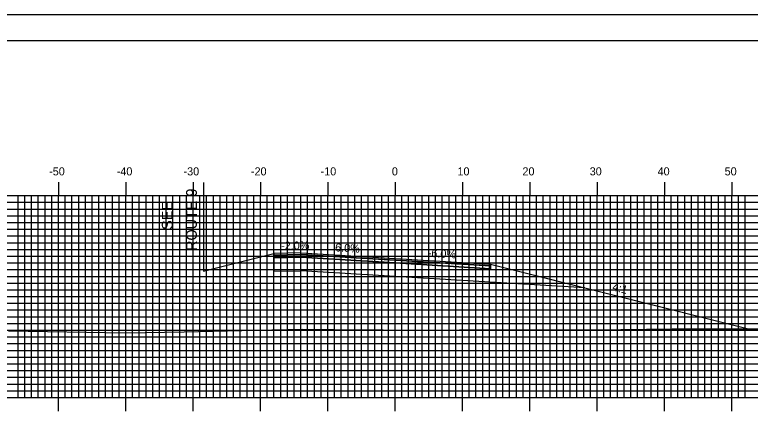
# Model space of a CAD drawing. Extents: x 2059 to 2403, y -1658 to -1438.
# Drawn here: x 2168.7 to 2277.9, y -1497.1 to -1437.7 of the extents above; entities that cross this region are included whole.
import ezdxf

# ---------------------------------------------------------------- set-up
doc = ezdxf.new("R2010")
doc.units = 0
for name, color, linetype in [('ANNOTATION', 7, 'Continuous'), ('BORDER', 7, 'Continuous'), ('D_Roadway_Centerline', 7, 'Continuous'), ('D_Roadway_Edge_Shoulder', 7, 'Continuous'), ('D_Roadway_Edge_TW', 7, 'Continuous'), ('D_Roadway_Pavement', 7, 'Continuous'), ('D_Roadway_SlopeLines', 7, 'Continuous'), ('D_Roadway_SubGrade', 7, 'Continuous'), ('H_V ANNOTATION', 7, 'Continuous'), ('MAJOR', 7, 'Continuous'), ('MINOR', 7, 'Continuous'), ('PLOT BOUNDARY', 7, 'Continuous'), ('S_Roadway_Centerline', 7, 'Continuous')]:
    doc.layers.add(name, color=color, linetype=linetype)

msp = doc.modelspace()

# ---------------------------------------------------------------- linework, layer by layer
at = {"layer": 'BORDER'}
msp.add_lwpolyline([(2075.59, -1651.6), (2395.59, -1651.6), (2395.59, -1441.6), (2075.59, -1441.6)], close=True, dxfattribs=at)
at = {"layer": 'D_Roadway_Centerline'}
msp.add_lwpolyline([(2196.7, -1475.81), (2198.84, -1475.27), (2207.19, -1473.19)], dxfattribs=at)
at = {"layer": 'D_Roadway_Edge_Shoulder'}
for points in [[(2211.19, -1473.11), (2207.19, -1473.19), (2207.19, -1473.44), (2211.19, -1473.36)], [(2211.19, -1473.11), (2207.19, -1473.19), (2207.19, -1473.44), (2211.19, -1473.36)], [(2225.19, -1473.95), (2239.33, -1474.8), (2239.33, -1475.05), (2225.19, -1474.2)]]:
    msp.add_lwpolyline(points, close=True, dxfattribs=at)
at = {"layer": 'D_Roadway_Edge_TW'}
msp.add_lwpolyline([(2211.19, -1473.11), (2225.19, -1473.95), (2225.19, -1474.2), (2211.19, -1473.36)], close=True, dxfattribs=at)
msp.add_lwpolyline([(2211.19, -1473.11), (2225.19, -1473.95), (2225.19, -1474.2), (2211.19, -1473.36)], close=True, dxfattribs=at)
msp.add_lwpolyline([(2211.19, -1473.11), (2225.19, -1473.95), (2225.19, -1474.2), (2211.19, -1473.36)], close=True, dxfattribs=at)
msp.add_lwpolyline([(2211.19, -1473.11), (2225.19, -1473.95), (2225.19, -1474.2), (2211.19, -1473.36)], close=True, dxfattribs=at)
at = {"layer": 'D_Roadway_Pavement'}
for points in [[(2211.19, -1473.36), (2207.19, -1473.44), (2207.19, -1473.85), (2211.19, -1473.77)], [(2211.19, -1473.36), (2207.19, -1473.44), (2207.19, -1473.85), (2211.19, -1473.77)], [(2211.19, -1473.36), (2225.19, -1474.2), (2225.19, -1474.61), (2211.19, -1473.77)], [(2211.19, -1473.36), (2225.19, -1474.2), (2225.19, -1474.61), (2211.19, -1473.77)], [(2211.19, -1473.36), (2225.19, -1474.2), (2225.19, -1474.61), (2211.19, -1473.77)], [(2211.19, -1473.36), (2225.19, -1474.2), (2225.19, -1474.61), (2211.19, -1473.77)], [(2225.19, -1474.2), (2239.33, -1475.05), (2239.33, -1475.46), (2225.19, -1474.61)]]:
    msp.add_lwpolyline(points, close=True, dxfattribs=at)
msp.add_lwpolyline([(2225.19, -1474.2), (2225.19, -1474.61)], dxfattribs=at)
msp.add_lwpolyline([(2225.19, -1474.2), (2225.19, -1474.61)], dxfattribs=at)
msp.add_lwpolyline([(2225.19, -1474.2), (2225.19, -1474.61)], dxfattribs=at)
msp.add_lwpolyline([(2225.19, -1474.2), (2225.19, -1474.61)], dxfattribs=at)
msp.add_lwpolyline([(2225.19, -1474.2), (2225.19, -1474.61)], dxfattribs=at)
msp.add_lwpolyline([(2225.19, -1474.2), (2225.19, -1474.61)], dxfattribs=at)
msp.add_lwpolyline([(2225.19, -1474.2), (2225.19, -1474.61)], dxfattribs=at)
msp.add_lwpolyline([(2225.19, -1474.2), (2225.19, -1474.61)], dxfattribs=at)
msp.add_lwpolyline([(2225.19, -1474.2), (2225.19, -1474.61)], dxfattribs=at)
msp.add_lwpolyline([(2225.19, -1474.2), (2225.19, -1474.61)], dxfattribs=at)
msp.add_lwpolyline([(2225.19, -1474.2), (2225.19, -1474.61)], dxfattribs=at)
msp.add_lwpolyline([(2225.19, -1474.2), (2225.19, -1474.61)], dxfattribs=at)
msp.add_lwpolyline([(2225.19, -1474.2), (2225.19, -1474.61)], dxfattribs=at)
msp.add_lwpolyline([(2225.19, -1474.2), (2225.19, -1474.61)], dxfattribs=at)
at = {"layer": 'D_Roadway_SlopeLines'}
msp.add_lwpolyline([(2239.33, -1474.8), (2277.67, -1484.38)], dxfattribs=at)
at = {"layer": 'D_Roadway_SubGrade'}
msp.add_line((2196.7, -1462.67), (2196.7, -1475.81), dxfattribs=at)
for points in [[(2211.19, -1473.77), (2207.19, -1473.85), (2207.19, -1473.44), (2207.19, -1475.85), (2211.19, -1475.77)], [(2211.19, -1473.77), (2225.19, -1474.61), (2225.19, -1476.61), (2211.19, -1475.77)], [(2211.19, -1473.77), (2225.19, -1474.61), (2225.19, -1476.61), (2211.19, -1475.77)], [(2211.19, -1473.77), (2225.19, -1474.61), (2225.19, -1476.61), (2211.19, -1475.77)], [(2211.19, -1473.77), (2225.19, -1474.61), (2225.19, -1476.61), (2211.19, -1475.77)], [(2225.19, -1474.61), (2225.19, -1474.2), (2239.33, -1475.05), (2239.33, -1474.8), (2253.37, -1478.3), (2225.19, -1476.61)], [(2225.19, -1474.61), (2225.19, -1474.2), (2239.33, -1475.05), (2239.33, -1474.8), (2253.37, -1478.3), (2225.19, -1476.61)], [(2225.19, -1474.61), (2239.33, -1475.46), (2239.33, -1475.05), (2239.33, -1474.8), (2253.37, -1478.3), (2225.19, -1476.61)]]:
    msp.add_lwpolyline(points, close=True, dxfattribs=at)
at = {"layer": 'MAJOR'}
for p, q in [((2175.19, -1462.6), (2175.19, -1464.6)), ((2185.19, -1462.6), (2185.19, -1464.6)), ((2195.19, -1462.6), (2195.19, -1464.6)), ((2205.19, -1462.6), (2205.19, -1464.6)), ((2215.19, -1462.6), (2215.19, -1464.6)), ((2225.19, -1462.6), (2225.19, -1464.6)), ((2235.19, -1462.6), (2235.19, -1464.6)), ((2245.19, -1462.6), (2245.19, -1464.6)), ((2255.19, -1462.6), (2255.19, -1464.6)), ((2265.19, -1462.6), (2265.19, -1464.6)), ((2275.19, -1462.6), (2275.19, -1464.6)), ((2085.19, -1464.6), (2365.19, -1464.6)), ((2085.19, -1464.6), (2365.19, -1464.6)), ((2175.19, -1494.6), (2175.19, -1464.6)), ((2185.19, -1494.6), (2185.19, -1464.6)), ((2195.19, -1494.6), (2195.19, -1464.6)), ((2205.19, -1494.6), (2205.19, -1464.6)), ((2215.19, -1494.6), (2215.19, -1464.6)), ((2225.19, -1494.6), (2225.19, -1464.6)), ((2235.19, -1494.6), (2235.19, -1464.6)), ((2245.19, -1494.6), (2245.19, -1464.6)), ((2255.19, -1494.6), (2255.19, -1464.6)), ((2265.19, -1494.6), (2265.19, -1464.6)), ((2275.19, -1494.6), (2275.19, -1464.6)), ((2085.19, -1469.6), (2365.19, -1469.6)), ((2085.19, -1474.6), (2365.19, -1474.6)), ((2085.19, -1479.6), (2365.19, -1479.6)), ((2085.19, -1484.6), (2365.19, -1484.6)), ((2085.19, -1489.6), (2365.19, -1489.6)), ((2085.19, -1494.6), (2365.19, -1494.6)), ((2085.19, -1494.6), (2365.19, -1494.6)), ((2175.19, -1496.61), (2175.19, -1494.6)), ((2185.19, -1496.61), (2185.19, -1494.6)), ((2195.19, -1496.61), (2195.19, -1494.6)), ((2205.19, -1496.61), (2205.19, -1494.6)), ((2215.19, -1496.61), (2215.19, -1494.6)), ((2225.19, -1496.61), (2225.19, -1494.6)), ((2235.19, -1496.61), (2235.19, -1494.6)), ((2245.19, -1496.61), (2245.19, -1494.6)), ((2255.19, -1496.61), (2255.19, -1494.6)), ((2265.19, -1496.61), (2265.19, -1494.6)), ((2275.19, -1496.61), (2275.19, -1494.6))]:
    msp.add_line(p, q, dxfattribs=at)
at = {"layer": 'MINOR'}
for p, q in [((2169.19, -1494.6), (2169.19, -1464.6)), ((2170.19, -1494.6), (2170.19, -1464.6)), ((2171.19, -1494.6), (2171.19, -1464.6)), ((2172.19, -1494.6), (2172.19, -1464.6)), ((2173.19, -1494.6), (2173.19, -1464.6)), ((2174.19, -1494.6), (2174.19, -1464.6)), ((2176.19, -1494.6), (2176.19, -1464.6)), ((2177.19, -1494.6), (2177.19, -1464.6)), ((2178.19, -1494.6), (2178.19, -1464.6)), ((2179.19, -1494.6), (2179.19, -1464.6)), ((2180.19, -1494.6), (2180.19, -1464.6)), ((2181.19, -1494.6), (2181.19, -1464.6)), ((2182.19, -1494.6), (2182.19, -1464.6)), ((2183.19, -1494.6), (2183.19, -1464.6)), ((2184.19, -1494.6), (2184.19, -1464.6)), ((2186.19, -1494.6), (2186.19, -1464.6)), ((2187.19, -1494.6), (2187.19, -1464.6)), ((2188.19, -1494.6), (2188.19, -1464.6)), ((2189.19, -1494.6), (2189.19, -1464.6)), ((2190.19, -1494.6), (2190.19, -1464.6)), ((2191.19, -1494.6), (2191.19, -1464.6)), ((2192.19, -1494.6), (2192.19, -1464.6)), ((2193.19, -1494.6), (2193.19, -1464.6)), ((2194.19, -1494.6), (2194.19, -1464.6)), ((2196.19, -1494.6), (2196.19, -1464.6)), ((2197.19, -1494.6), (2197.19, -1464.6)), ((2198.19, -1494.6), (2198.19, -1464.6)), ((2199.19, -1494.6), (2199.19, -1464.6)), ((2200.19, -1494.6), (2200.19, -1464.6)), ((2201.19, -1494.6), (2201.19, -1464.6)), ((2202.19, -1494.6), (2202.19, -1464.6)), ((2203.19, -1494.6), (2203.19, -1464.6)), ((2204.19, -1494.6), (2204.19, -1464.6)), ((2206.19, -1494.6), (2206.19, -1464.6)), ((2207.19, -1494.6), (2207.19, -1464.6)), ((2208.19, -1494.6), (2208.19, -1464.6)), ((2209.19, -1494.6), (2209.19, -1464.6)), ((2210.19, -1494.6), (2210.19, -1464.6)), ((2211.19, -1494.6), (2211.19, -1464.6)), ((2212.19, -1494.6), (2212.19, -1464.6)), ((2213.19, -1494.6), (2213.19, -1464.6)), ((2214.19, -1494.6), (2214.19, -1464.6)), ((2216.19, -1494.6), (2216.19, -1464.6)), ((2217.19, -1494.6), (2217.19, -1464.6)), ((2218.19, -1494.6), (2218.19, -1464.6)), ((2219.19, -1494.6), (2219.19, -1464.6)), ((2220.19, -1494.6), (2220.19, -1464.6)), ((2221.19, -1494.6), (2221.19, -1464.6)), ((2222.19, -1494.6), (2222.19, -1464.6)), ((2223.19, -1494.6), (2223.19, -1464.6)), ((2224.19, -1494.6), (2224.19, -1464.6)), ((2226.19, -1494.6), (2226.19, -1464.6)), ((2227.19, -1494.6), (2227.19, -1464.6)), ((2228.19, -1494.6), (2228.19, -1464.6)), ((2229.19, -1494.6), (2229.19, -1464.6)), ((2230.19, -1494.6), (2230.19, -1464.6)), ((2231.19, -1494.6), (2231.19, -1464.6)), ((2232.19, -1494.6), (2232.19, -1464.6)), ((2233.19, -1494.6), (2233.19, -1464.6)), ((2234.19, -1494.6), (2234.19, -1464.6)), ((2236.19, -1494.6), (2236.19, -1464.6)), ((2237.19, -1494.6), (2237.19, -1464.6)), ((2238.19, -1494.6), (2238.19, -1464.6)), ((2239.19, -1494.6), (2239.19, -1464.6)), ((2240.19, -1494.6), (2240.19, -1464.6)), ((2241.19, -1494.6), (2241.19, -1464.6)), ((2242.19, -1494.6), (2242.19, -1464.6)), ((2243.19, -1494.6), (2243.19, -1464.6)), ((2244.19, -1494.6), (2244.19, -1464.6)), ((2246.19, -1494.6), (2246.19, -1464.6)), ((2247.19, -1494.6), (2247.19, -1464.6)), ((2248.19, -1494.6), (2248.19, -1464.6)), ((2249.19, -1494.6), (2249.19, -1464.6)), ((2250.19, -1494.6), (2250.19, -1464.6)), ((2251.19, -1494.6), (2251.19, -1464.6)), ((2252.19, -1494.6), (2252.19, -1464.6)), ((2253.19, -1494.6), (2253.19, -1464.6)), ((2254.19, -1494.6), (2254.19, -1464.6)), ((2256.19, -1494.6), (2256.19, -1464.6)), ((2257.19, -1494.6), (2257.19, -1464.6)), ((2258.19, -1494.6), (2258.19, -1464.6)), ((2259.19, -1494.6), (2259.19, -1464.6)), ((2260.19, -1494.6), (2260.19, -1464.6)), ((2261.19, -1494.6), (2261.19, -1464.6)), ((2262.19, -1494.6), (2262.19, -1464.6)), ((2263.19, -1494.6), (2263.19, -1464.6)), ((2264.19, -1494.6), (2264.19, -1464.6)), ((2266.19, -1494.6), (2266.19, -1464.6)), ((2267.19, -1494.6), (2267.19, -1464.6)), ((2268.19, -1494.6), (2268.19, -1464.6)), ((2269.19, -1494.6), (2269.19, -1464.6)), ((2270.19, -1494.6), (2270.19, -1464.6)), ((2271.19, -1494.6), (2271.19, -1464.6)), ((2272.19, -1494.6), (2272.19, -1464.6)), ((2273.19, -1494.6), (2273.19, -1464.6)), ((2274.19, -1494.6), (2274.19, -1464.6)), ((2276.19, -1494.6), (2276.19, -1464.6)), ((2277.19, -1494.6), (2277.19, -1464.6)), ((2085.19, -1465.6), (2365.19, -1465.6)), ((2085.19, -1466.6), (2365.19, -1466.6)), ((2085.19, -1467.6), (2365.19, -1467.6)), ((2085.19, -1468.6), (2365.19, -1468.6)), ((2085.19, -1470.6), (2365.19, -1470.6)), ((2085.19, -1471.6), (2365.19, -1471.6)), ((2085.19, -1472.6), (2365.19, -1472.6)), ((2085.19, -1473.6), (2365.19, -1473.6)), ((2085.19, -1475.6), (2365.19, -1475.6)), ((2085.19, -1476.6), (2365.19, -1476.6)), ((2085.19, -1477.6), (2365.19, -1477.6)), ((2085.19, -1478.6), (2365.19, -1478.6)), ((2085.19, -1480.6), (2365.19, -1480.6)), ((2085.19, -1481.6), (2365.19, -1481.6)), ((2085.19, -1482.6), (2365.19, -1482.6)), ((2085.19, -1483.6), (2365.19, -1483.6)), ((2085.19, -1485.6), (2365.19, -1485.6)), ((2085.19, -1486.6), (2365.19, -1486.6)), ((2085.19, -1487.6), (2365.19, -1487.6)), ((2085.19, -1488.6), (2365.19, -1488.6)), ((2085.19, -1490.6), (2365.19, -1490.6)), ((2085.19, -1491.6), (2365.19, -1491.6)), ((2085.19, -1492.6), (2365.19, -1492.6)), ((2085.19, -1493.6), (2365.19, -1493.6))]:
    msp.add_line(p, q, dxfattribs=at)
at = {"layer": 'PLOT BOUNDARY'}
msp.add_lwpolyline([(2059.4, -1657.72), (2399.4, -1657.72), (2399.4, -1437.72), (2059.4, -1437.72)], close=True, dxfattribs=at)
at = {"layer": 'S_Roadway_Centerline'}
msp.add_lwpolyline([(2167.74, -1484.69), (2185.15, -1484.97), (2193.87, -1484.85), (2204.55, -1484.58), (2211.5, -1484.43), (2220.92, -1484.57), (2223.43, -1484.55), (2225.24, -1484.58), (2234.74, -1484.55), (2247.42, -1484.56), (2258.69, -1484.5), (2266.3, -1484.39), (2275.15, -1484.38), (2286.77, -1484.42)], dxfattribs=at)

# ---------------------------------------------------------------- texts
at = {"layer": 'ANNOTATION'}
for s, height, rotation, p in [('ROUTE 9', 1.6, 90, (2195.74, -1472.83)), ('SEE', 1.6, 90, (2192.14, -1469.69)), ('-2.0%', 1.2, 1.1458, (2208.26, -1472.66)), ('6.0%', 1.2, 356.5664, (2216.25, -1472.88)), ('-6.0%', 1.2, 356.5664, (2230, -1473.7)), ('4:1', 1.2, 345.9638, (2257.36, -1478.68))]:
    msp.add_text(s, height=height, rotation=rotation, dxfattribs=at).set_placement(p)
at = {"layer": 'H_V ANNOTATION'}
for s, p in [('-50', (2173.8, -1461.6)), ('-40', (2183.84, -1461.6)), ('-30', (2193.76, -1461.6)), ('-20', (2203.77, -1461.6)), ('-10', (2214.12, -1461.6)), ('0', (2224.7, -1461.6)), ('10', (2234.44, -1461.6)), ('20', (2244.09, -1461.6)), ('30', (2254.08, -1461.6)), ('40', (2264.16, -1461.6)), ('50', (2274.12, -1461.6))]:
    msp.add_text(s, height=1.2, dxfattribs=at).set_placement(p)

doc.saveas('drawing.dxf')
